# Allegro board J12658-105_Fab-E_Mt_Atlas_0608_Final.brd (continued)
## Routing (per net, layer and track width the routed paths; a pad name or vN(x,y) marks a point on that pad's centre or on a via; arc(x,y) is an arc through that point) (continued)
AP_I2C1_SCL: length 72.6
  TOP w0.127: v1(15.62,37.85) 15.62,38.1 16.04,38.52 U19.6 ; U22.D11 v1(30.98,44.37)
  L3_SIG w0.127: v1(14.59,48.38) 14.34,48.13 14.34,43.5 14.93,42.91 14.93,39.89 15.19,39.64 15.19,38.48 15.62,38.05 v1(15.62,37.85) ; v1(29.9,49.94) 29.9,47.44 30.59,46.75 30.59,44.92 30.98,44.52 v1(30.98,44.37) ; v1(14.61,12.7) 11.85,15.46 11.85,36.37 11.68,36.54 11.68,36.57 11.49,36.76 v1(11.49,38.04)
  L4_SIG w0.127: v1(15.62,37.85) 14.7,36.92 12.61,36.92 v1(11.49,38.04) ; v1(14.59,48.38) 14.79,48.38 15.02,48.61 15.2,48.61 15.95,49.36 17.84,49.36 18.03,49.18 18.16,49.05 19.25,49.05 19.89,49.05 20.28,48.66 22.25,48.66 22.74,49.15 24.79,49.15 25.16,49.52 27.82,49.52 28.22,49.12 28.77,49.12 29.59,49.94 v1(29.9,49.94)
  BOTTOM w0.127: R244.1 v1(14.61,12.7) ; R179.2 29.23,45.89 30.02,45.89 30.59,45.32 30.59,44.88 30.98,44.48 v1(30.98,44.37)
AP_I2C1_SCL_HDR: length 13.3
  BOTTOM w0.203: R244.2 12.51,12.7 10.9,11.09 9.5,11.09 8.95,10.54 8.95,9.4 8.45,8.89 3.81,8.89 J15.39
AP_I2C1_SDA: length 72.9
  TOP w0.127: U19.3 21,40.47 v1(21.59,39.88) ; U22.C11 v1(30.18,44.37)
  L3_SIG w0.127: v1(21.59,39.88) 23.79,42.08 23.79,44.83 24.31,45.34 v1(24.64,45.34) ; v1(7.9,40.79) 7.48,40.37 7.48,37.22 8.34,36.36 8.34,35.06 8.25,34.97 8.25,26.49 8.34,26.39 8.34,26 7.98,25.63 7.98,25.57 7.97,25.56 7.97,13.05 7.98,13.04 7.98,12.98 9.73,11.23 10.81,11.23 12.24,9.8 14.01,9.8 v1(14.67,9.14)
  L4_SIG w0.127: v1(7.9,40.79) 9.24,39.44 13.41,39.44 14.24,40.27 21.01,40.27 21.41,39.88 v1(21.59,39.88) ; v1(30.18,44.37) 30.1,44.37 29.7,44.77 29.23,44.77 28.99,45 28.99,45.32 28.58,45.73 25.03,45.73 v1(24.64,45.34)
  BOTTOM w0.127: R256.1 v1(14.67,9.14) ; R182.2 25.53,45.72 25.15,45.34 v1(24.64,45.34)
AP_I2C1_SDA_HDR: length 12.7
  BOTTOM w0.203: R256.2 12.51,9.14 11.3,7.94 11.3,7.11 10.7,6.51 3.97,6.51 2.54,5.08
AP_I2C1_SS_SCL: length 106
  TOP w0.127: U22.D10 v1(30.98,43.57) ; U19.5 18.36,39.17 v1(18.67,38.86) ; R116.2 54.8,11.43 v1(54.74,11.37) ; v1(22.96,48.63) 22.99,48.66 R30.1
  L3_SIG w0.127: v1(18.86,9.27) 18.86,9.33 19.11,9.58 19.11,10.86 18.85,11.13 18.85,16.81 19.04,17 19.04,27.32 17.92,28.44 17.92,31.92 18.26,32.26 18.54,32.26 18.88,32.6 18.88,32.96 18.28,33.57 18.28,34.18 18.81,34.71 18.81,35.93 18.28,36.46 18.28,36.99 18.62,37.34 18.72,37.34 19.06,37.68 19.06,38.47 v1(18.67,38.86) 17.26,40.27 v1(17.26,48.9) ; v1(30.98,43.57) 30.98,43.74 30.58,44.14 30.58,44.53 30.35,44.76 30.02,44.76 29.78,45 29.78,45.97 28.26,47.5 v1(28.26,48.26) ; v1(54.74,11.37) 54.74,12.32 54.46,12.6 53.67,12.6 52.88,11.81 52.88,10.57 53.02,10.43 v1(53.02,9.62)
  L4_SIG w0.127: v1(17.26,48.9) 17.35,48.82 18.07,48.82 19.16,48.82 19.16,48.82 19.8,48.82 20.18,48.43 20.32,48.43 22.76,48.43 v1(22.96,48.63) 24.59,48.63 25.26,49.29 26.03,49.29 26.43,48.89 27.63,48.89 v1(28.26,48.26) ; v1(53.02,9.62) 52.68,9.62 52.62,9.68 48.39,9.68 47.87,9.16 47.01,9.16 46.58,9.59 37.15,9.59 37.02,9.46 19.24,9.46 19.05,9.27 v1(18.86,9.27)
  BOTTOM w0.127: R187.2 v1(18.67,38.86)
AP_I2C1_SS_SCL_HDR: length 10.2
  TOP w0.203: J14.44 64.77,11.43 R116.1
AP_I2C1_SS_SCL_IMU: length 2.6
  TOP w0.127: R30.2 R28.2 24.33,50.8 24.58,50.55 U14.3
AP_I2C1_SS_SDA: length 111.5
  TOP w0.127: v1(24.64,51.97) 23.91,52.7 R25.1 ; U22.C10 v1(30.18,43.57) ; R112.2 v1(54.61,13.78) ; U19.2 18.44,41.12 v1(18.67,40.89)
  L3_SIG w0.127: v1(24.64,51.97) 26.61,50 26.61,47.37 28.02,45.96 28.02,45.17 28.43,44.76 28.74,44.76 28.98,44.52 28.98,44.21 29.22,43.97 29.6,43.97 30,43.57 v1(30.18,43.57) ; v1(18.41,6.47) 19.3,7.36 19.3,9.45 19.34,9.49 19.34,10.96 19.21,11.09 19.09,11.21 19.09,16.73 19.27,16.9 19.27,27.41 18.15,28.53 18.15,31.09 18.52,31.46 18.58,31.46 19.13,32.01 19.13,37.33 19.29,37.49 19.29,39.06 18.97,39.38 18.97,40.59 v1(18.67,40.89) ; v1(52.32,8.95) 52.32,9.52 52.62,9.82 52.62,11.87 53.58,12.83 54.08,12.83 54.61,13.36 v1(54.61,13.78) ; v1(24.32,40.54) 24.32,40.89 25.03,41.6 25.03,41.94 24.68,42.3 24.68,44.37 v1(24.39,44.66)
  L4_SIG w0.127: v1(52.32,8.95) 51.37,8 49.44,8 48.59,7.15 37.47,7.15 36.32,8.29 34.11,8.29 32.68,6.86 18.8,6.86 18.42,6.47 v1(18.41,6.47) ; v1(24.39,44.66) 25.13,44.66 25.41,44.95 26.53,44.95 26.71,44.76 28.75,44.76 28.98,44.53 28.98,44.22 29.22,43.97 29.78,43.97 v1(30.18,43.57) ; v1(24.32,40.54) 24.27,40.49 22.6,40.49 22.59,40.5 21.43,40.5 21.04,40.89 v1(18.67,40.89)
  BOTTOM w0.127: R191.2 v1(18.67,40.89)
AP_I2C1_SS_SDA_HDR: length 10.3
  TOP w0.203: R112.1 57.89,13.78 58.08,13.97 64.77,13.97 66.04,12.7
AP_I2C1_SS_SDA_IMU: length 3
  TOP w0.127: R24.2 R25.2 24.64,51.05 U14.2
AP_JTAG_TCK: length 25.7
  TOP w0.127: v1(31.5,56.26) 31.8,56.57 U13.15 ; U22.G2 v1(34.18,37.17)
  L3_SIG w0.127: v1(34.18,37.17) 33.27,38.08 33.27,39.06 33.44,39.22 33.44,39.93 33.35,40.01 33.35,45.9 31.69,47.56 31.69,49.78 30.76,50.71 30.76,55.83 31.19,56.26 v1(31.5,56.26)
  BOTTOM w0.127: v1(31.5,56.26) 30.99,56.77 30.99,57.91 30.86,58.04 R274.1
AP_JTAG_TDI: length 28.3
  TOP w0.127: U13.14 31.8,56.97 v1(31.5,57.28) ; U22.G4 v1(34.18,38.77)
  L3_SIG w0.127: v1(31.5,57.28) 30.96,57.28 30.53,56.84 30.53,50.61 31.43,49.71 31.43,47.43 33.12,45.75 33.12,39.92 33.21,39.83 33.21,39.31 33.02,39.12 33.02,37.86 33.69,37.19 33.69,37.05 34.08,36.66 34.33,36.66 34.58,36.91 34.58,38.37 v1(34.18,38.77)
  BOTTOM w0.127: v1(31.5,57.28) 32.26,57.28 R129.2
AP_JTAG_TDO: length 26.5
  TOP w0.127: v1(47.56,45.08) 48.49,45.08 U17.13 ; U22.H3 v1(34.98,37.17)
  L3_SIG w0.127: v1(34.87,46.69) 35.51,46.06 35.51,45.1 35.38,44.97 35.38,41.66 34.58,40.86 34.58,39.4 34.82,39.16 35.15,39.16 35.38,38.93 35.38,37.73 34.98,37.33 v1(34.98,37.17)
  L4_SIG w0.127: v1(34.87,46.69) 41.19,46.69 42.42,45.47 46.79,45.47 46.83,45.43 47.22,45.43 v1(47.56,45.08)
  BOTTOM w0.254: R277.2 v1(47.56,45.08)
AP_JTAG_TMS: length 25.6
  TOP w0.127: U22.G3 v1(34.18,37.97) ; U13.13 32.17,57.37 31.88,57.66 31.88,57.91 v1(31.5,58.29)
  L3_SIG w0.127: v1(34.18,37.97) 33.58,38.57 33.58,39.04 33.67,39.13 33.67,40.02 33.58,40.11 33.58,46.05 31.94,47.69 31.94,49.85 30.99,50.8 30.99,55.65 31.09,55.75 31.7,55.75 32.1,56.16 32.1,57.56 31.5,58.17 v1(31.5,58.29)
  BOTTOM w0.127: v1(31.5,58.29) 31.75,58.55 R275.2
AP_JTAG_TRST_N: length 28.1
  TOP w0.127: U22.G1 33.78,35.24 v1(33.85,35.18) ; U13.12 v1(32.93,58.29)
  L3_SIG w0.127: v1(32.93,58.29) 33.99,57.23 33.99,54.21 36.18,52.02 36.18,41.66 35.39,40.87 35.39,39.4 35.67,39.13 35.67,37.61 35.39,37.33 35.39,37.02 33.85,35.47 v1(33.85,35.18)
  BOTTOM w0.127: v1(32.93,58.29) 32.64,58.58 R276.1
AP_PWRGOOD: length 29.5
  TOP w0.127: v1(45.97,44.77) 45.4,44.77 45.01,45.16 U26.1 ; U22.G5 v1(34.18,39.57)
  L3_SIG w0.127: v1(45.97,44.77) 45.97,44.45 47.62,42.8 47.62,37.78 48.13,37.27 48.13,36.26 47.82,35.94 47.13,35.94 v1(47.12,35.95)
  L4_SIG w0.127: v1(34.18,39.57) 34.59,39.16 34.59,37.8 34.82,37.57 37.65,37.57 39.34,35.89 42.66,35.89 43.6,34.95 46.11,34.95 v1(47.12,35.95)
AP_PWRGOOD_SENSE: length 2.4
  TOP w0.203: U26.2 45.66,46 45.81,45.85 C101.1
  TOP w0.254: R5.2 C101.1
AP_RESET_N: length 85.2
  TOP w0.127: v1(64.64,70.87) 64.14,70.87 63.82,71.18 63.82,71.5 63.38,71.94 U36.4
  L3_SIG w0.127: v1(21.59,40.9) 22.01,40.9 23.5,42.39 23.5,46.04 22.45,47.08 22.45,48.9 22.78,49.23 22.78,53.89 22.23,54.45 22.23,62.94 21.35,63.82 21.35,64.53 21.72,64.9 v1(21.72,66.46)
  L4_SIG w0.127: v1(21.72,66.46) 22.81,66.46 23.48,67.13 24.82,67.13 25.51,66.44 34.64,66.44 34.79,66.6 50.85,66.6 52.13,67.88 52.13,68.58 52.58,69.02 56.06,69.02 56.72,69.68 59.73,69.68 60.59,68.82 62.08,68.82 62.87,69.61 62.87,69.65 64.09,70.87 v1(64.64,70.87)
  BOTTOM w0.127: U32.2 65.96,68.37 65.6,68.01 64.45,68.01 64.07,68.39 64.07,70.23 64.64,70.8 v1(64.64,70.87) 65.26,70.25 U32.5 ; v1(21.59,40.9) 21.6,40.89 R281.1
AP_RESET_N_R: length 10.4
  TOP w0.127: U22.E5 32.18,39.17 v1(31.79,38.77)
  L4_SIG w0.127: v1(25.07,40.99) 25.27,40.79 26.46,40.79 27.04,40.21 30.9,40.21 31.38,39.73 31.38,39.18 v1(31.79,38.77)
  BOTTOM w0.127: v1(25.07,40.99) 24.2,40.99 24.1,40.89 R281.2
AP_RESET_N_VSYS: length 4.3
  TOP w0.127: v1(63.44,69.66) 63.38,69.72 U36.3
  BOTTOM w0.127: v1(63.44,69.66) 63.82,70.04 63.82,70.62 64.82,71.62 U31.1
AP_SPI0_SS_CS0_N: length 42.7
  TOP w0.127: v1(26.62,53.57) 26.78,53.57 27.41,52.95 27.41,52.55 27.11,52.25 U14.12 ; v1(25.1,42.43) 25.36,42.7 28.65,42.7 U22.A9 ; R41.1 10.05,44.83 10.16,44.72 v1(10.16,42.16)
  L3_SIG w0.127: v1(23.24,53.59) 23.24,53.36 23.12,53.24 23.12,50.3 23.43,49.99 23.43,47.95 23.43,47.55 23.43,47.36 25.1,45.69 v1(25.1,42.43)
  L4_SIG w0.127: v1(26.62,53.57) 26.28,53.91 23.56,53.91 v1(23.24,53.59) ; v1(25.1,42.43) 25.1,41.68 24.77,41.35 11.29,41.35 10.48,42.16 v1(10.16,42.16)
  BOTTOM w0.127: v1(26.62,53.57) 26.68,53.57 26.7,53.59 R152.2
AP_SPI0_SS_CS0_N_HDR: length 6.6
  TOP w0.203: R41.2 6.48,44.83 6.1,44.45 3.81,44.45 J15.9
AP_SPI0_SS_CS1_N: length 27.7
  TOP w0.127: U22.D9 v1(30.98,42.77) ; v1(14.86,43.56) 14.86,42.48 13.91,41.53 R46.1
  L4_SIG w0.127: v1(14.86,43.56) 15.57,42.85 16.92,42.85 17.69,42.08 20.96,42.08 21.32,42.44 21.32,42.58 21.55,42.81 21.69,42.81 22.26,43.38 27.08,43.38 28.09,42.37 30.5,42.37 30.89,42.77 v1(30.98,42.77)
  BOTTOM w0.127: R180.2 27.93,46.17 28.55,46.17 29.16,45.56 29.55,45.56 29.79,45.32 29.79,45 30.03,44.76 30.35,44.76 30.59,44.52 30.59,43.16 v1(30.98,42.77)
AP_SPI0_SS_CS1_N_HDR: length 10.5
  TOP w0.203: J15.11 3.81,41.91 5.97,41.91 6.22,41.66 11.58,41.66 11.71,41.53 R46.2
AP_SPI0_SS_CS2_N_GPIO29: length 69.8
  TOP w0.127: v1(15.75,43.56) 15.75,42.93 14.99,42.17 14.99,40.16 14.33,39.5 R50.1 ; R86.1 v1(43.05,25.65) ; U22.B9 v1(29.38,42.77)
  L3_SIG w0.127: v1(15.75,43.56) 16.24,43.07 16.24,39.71 16.32,39.63 16.32,32.58 15.43,31.69 15.43,31.13 15.44,31.12 15.44,30.79 15.43,30.78 v1(15.43,29.46) ; v1(41.66,28.96) 41.66,27.05 v1(43.05,25.65)
  L4_SIG w0.127: v1(41.66,28.96) 40.4,28.96 39.97,29.39 34.7,29.39 34.46,29.15 25.89,29.15 25.45,28.7 21.44,28.7 21.09,29.04 21.09,29.05 20.69,29.46 v1(15.43,29.46) ; v1(29.38,42.77) 28.02,42.77 27.53,43.26 27.18,43.61 22.36,43.61 22.35,43.62 22.16,43.62 21.59,43.05 21.46,43.05 21.08,42.67 21.08,42.54 20.84,42.3 17.79,42.3 16.53,43.56 v1(15.75,43.56)
  BOTTOM w0.127: R193.2 28.16,42.77 v1(29.38,42.77)
AP_SPI0_SS_CS2_N_GPIO29_HDR: length 10.3
  TOP w0.203: J15.13 3.8,39.38 11.63,39.38 11.75,39.5 12.32,39.5
AP_SPI0_SS_CS3_N_GPIO30: length 60.7
  TOP w0.127: v1(31.43,21.46) 31.88,21.46 32.2,21.79 U25.13 ; R56.1 v1(13.84,36.45) ; U22.C8 v1(30.18,41.97)
  L3_SIG w0.127: v1(13.84,36.45) 13.56,36.73 13.56,36.92 13.28,37.2 13.28,37.23 13.28,37.23 13.28,38.93 13.27,38.94 13.27,39.19 13.22,39.24 13.12,39.34 13.12,40.82 13.22,40.92 13.22,40.93 13.97,41.68 v1(13.97,42.54) ; v1(30.18,41.97) 30.18,41.78 30.58,41.39 30.58,41 29.71,40.13 28.59,40.13 27.5,39.05 27.5,37.99 26.67,37.15 26.67,36.71 26.35,36.4 26.35,35.49 26.36,35.49 26.36,32.84 24.54,31.02 24.54,29.53 22.75,27.74 22.75,27.47 22.72,27.44 22.72,23 v1(24.13,21.59)
  L4_SIG w0.127: v1(31.43,21.46) 30.68,22.21 30.6,22.29 24.83,22.29 v1(24.13,21.59) ; v1(13.97,42.54) 14.3,42.21 16.58,42.21 16.81,41.98 17.17,41.62 23.56,41.62 v1(24.25,42.32)
  BOTTOM w0.127: v1(30.18,41.97) 30.07,41.97 29.67,42.36 28.42,42.36 28.35,42.29 R194.2 27.54,42.29 27.1,42.74 26.02,42.74 25.78,42.98 24.91,42.98 v1(24.25,42.32)
AP_SPI0_SS_CS3_N_GPIO30_HDR: length 10.5
  TOP w0.203: 12.32,36.45 11.68,36.45 11.46,36.66 3.98,36.66 J15.15
AP_SPI0_SS_MISO: length 32.9
  TOP w0.127: U22.A10 v1(28.58,43.57) ; U14.1 25.34,52.06 v1(24.57,52.83) ; R32.1 9.91,49.66 10.16,49.4 v1(10.16,49.09)
  L3_SIG w0.127: v1(24.57,52.83) 24.38,52.64 24.37,52.64 23.96,52.23 23.96,51.44 25.1,50.3 25.1,49.49 24.74,49.13 24.74,48.31 26.89,46.16 26.89,44.89 28.21,43.57 v1(28.58,43.57)
  L4_SIG w0.127: v1(10.16,49.09) 14.95,49.09 16.36,50.5 17.36,50.5 18.27,49.58 19.52,49.58 19.83,49.9 21.66,49.9 21.95,49.61 22.37,49.61 22.95,50.18 22.95,51.21 v1(24.57,52.83)
AP_SPI0_SS_MISO_HDR: length 6.4
  TOP w0.203: J15.5 3.68,49.66 R32.2
AP_SPI0_SS_MOSI: length 36.1
  TOP w0.127: R37.1 9.91,47.12 v1(10.16,47.37) ; U22.B10 v1(29.38,43.57) ; U14.14 26.11,52.32 v1(25.59,52.83)
  L3_SIG w0.127: v1(25.59,52.83) 25.17,52.41 24.46,52.41 24.19,52.14 24.19,51.76 25.33,50.62 25.33,49.34 24.97,48.98 24.97,48.55 27.34,46.18 27.34,45.42 27.93,44.83 27.93,44.25 28.23,43.96 28.86,43.96 29.25,43.57 v1(29.38,43.57)
  L4_SIG w0.127: v1(10.16,47.37) 9.59,47.94 9.59,48.45 9.78,48.64 10.48,48.64 10.99,48.13 13.53,48.13 14.23,48.84 15.02,48.84 15.78,49.59 17.94,49.59 18.17,49.36 19.62,49.36 19.93,49.67 21.57,49.67 21.85,49.38 22.6,49.38 25.59,52.37 v1(25.59,52.83)
AP_SPI0_SS_MOSI_HDR: length 6.5
  TOP w0.203: J15.7 3.78,47.02 5.89,47.02 5.99,47.12 R37.2
AP_SPI0_SS_SCK: length 33.9
  TOP w0.127: U22.C9 v1(30.18,42.77) ; v1(10.16,51.5) 9.78,51.88 9.52,51.88 R23.1 ; U14.13 26.61,52.38 v1(27,52.78)
  L3_SIG w0.127: v1(27,52.78) 27.53,52.25 27.53,47.27 28.99,45.81 28.99,45 29.23,44.77 29.54,44.77 29.78,44.52 29.78,44.21 30.03,43.96 30.34,43.96 30.58,43.72 30.58,43.17 v1(30.18,42.77)
  L4_SIG w0.127: v1(27,52.78) 26.58,52.78 26.44,52.92 26.44,53.18 25.94,53.68 24.22,53.68 22.98,52.44 21.49,52.44 20.97,52.95 16.88,52.95 15.98,52.06 15.32,52.06 14.79,52.58 11.24,52.58 v1(10.16,51.5)
AP_SPI0_SS_SCK_HDR: length 6.4
  TOP w0.203: J15.3 3.8,52.08 7.43,52.08 R23.2
AP_SPI1_SS_CS0_N: length 38
  TOP w0.127: R93.1 v1(13.84,24.13) ; U23.2 v1(18.41,35.03) ; U22.C7 v1(30.18,41.17)
  L3_SIG w0.127: v1(18.41,35.03) 17.26,33.87 17.26,30.59 16.8,30.14 16.8,26.76 17.97,25.59 v1(17.97,25.08) ; v1(25.97,34.75) 25.97,36.41 26.44,36.88 26.44,37.25 26.44,37.25 27.22,38.03 27.22,39.09 27.28,39.14 27.28,39.23 28.4,40.36 28.5,40.36 28.52,40.39 29.4,40.39 v1(30.18,41.17)
  L4_SIG w0.127: v1(13.84,24.13) 17.46,24.13 17.97,24.64 v1(17.97,25.08) ; v1(25.97,34.75) 22.66,34.75 21.99,35.42 21.06,35.42 20.86,35.22 19.17,35.22 18.97,35.03 v1(18.41,35.03)
  BOTTOM w0.127: v1(30.18,41.17) 29.53,40.51 27.87,40.51 R201.2
AP_SPI1_SS_CS0_N_HDR: length 10.5
  TOP w0.203: J15.25 3.81,24.13 7.49,24.13 7.75,23.88 11.18,23.88 11.43,24.13 12.32,24.13
AP_SPI1_SS_CS1_N: length 33.1
  TOP w0.127: U22.A7 v1(28.58,41.17)
  L3_SIG w0.127: v1(22.03,23.62) 22.33,23.92 22.33,26.21 21.83,26.71 21.83,27.21 22.29,27.67 22.29,27.93 24.04,29.68 24.04,31.76 24.26,31.98 24.26,32.21 25.58,33.53 25.58,33.92 25.11,34.38 25.11,37.12 24.88,37.35 24.88,38.41 25.29,38.82 26.22,38.82 28.56,41.17 v1(28.58,41.17)
  L4_SIG w0.127: v1(22.03,23.62) 21.65,23.24 v1(13.84,23.24)
  BOTTOM w0.127: v1(28.58,41.17) 28.24,41.17 28.13,41.27 R200.2 ; v1(13.84,23.24) 13.97,23.11 R217.1
AP_SPI1_SS_CS1_N_HDR: length 15.2
  BOTTOM w0.203: J15.27 3.68,21.72 10.54,21.72 12.51,23.69 15.81,23.69 16,23.5 R217.2
AP_SPI1_SS_CS2_N_UART0_CTS_N: length 95.8
  TOP w0.127: U22.D8 v1(30.98,41.97) ; v1(21.81,21.15) 22.23,20.73 R266.1 ; v1(58.93,55.88) R19.1
  L3_SIG w0.127: v1(29.46,61.21) 30,60.68 30,54.58 30.07,54.51 30.07,53.75 30.07,50.42 30.92,49.57 30.92,46.8 31.36,46.36 31.36,45.48 31.38,45.47 31.38,45.14 31.38,45.14 31.38,42.6 31.36,42.59 31.36,42.35 v1(30.98,41.97) ; v1(21.72,42.42) 21.2,41.9 21.2,38.77 22.09,37.88 22.09,34.86 20.85,33.63 20.85,32.08 21.08,31.85 21.08,31.06 22,30.15 22,28.93 21.37,28.31 21.37,28.05 20.92,27.59 20.92,22.81 21.81,21.92 v1(21.81,21.15)
  L4_SIG w0.127: v1(58.93,55.88) 58.93,55.94 58.36,56.52 58.36,59.75 53.38,64.73 48.52,64.73 45.55,61.76 39.46,61.76 39.27,61.76 38.46,60.94 29.73,60.94 v1(29.46,61.21)
  BOTTOM w0.127: v1(30.98,41.97) 30.58,42.37 30.02,42.37 29.79,42.6 29.79,42.93 29.79,43.4 29.79,43.4 29.79,43.72 29.55,43.96 27.98,43.96 R190.2 27.18,44.77 25.34,44.77 24.7,44.13 22.61,44.13 21.72,43.24 v1(21.72,42.42)
AP_SPI1_SS_CS2_N_UART0_CTS_N_BLE: length 5.5
  TOP w0.127: R266.2 20.64,20 20.19,19.56 20.19,16.51 20.49,16.22 U30.26
AP_SPI1_SS_CS2_N_UART0_CTS_N_HDR: length 2.9
  TOP w0.203: R19.2 63.5,55.88
AP_SPI1_SS_CS3_N_UART0_RTS_N: length 80.8
  TOP w0.127: U22.D7 v1(30.98,41.17) ; R22.1 59.18,53.34 58.99,53.15 v1(58.99,52.9) ; R267.1 20.51,20.57 v1(21.08,21.15)
  L3_SIG w0.127: v1(58.99,52.9) 60.13,51.76 60.13,43.76 60.01,43.64 60.01,42.84 60.48,42.37 60.48,40.03 v1(60.2,39.75) ; v1(21.61,39.16) 22.31,38.46 22.31,33.98 21.08,32.74 21.08,32.19 21.69,31.57 21.75,31.57 22.22,31.1 22.22,28.84 21.6,28.22 21.6,27.96 21.15,27.5 21.15,22.9 22.2,21.85 22.2,20.99 21.97,20.76 21.47,20.76 v1(21.08,21.15)
  L4_SIG w0.127: v1(30.98,41.17) 31.39,40.76 36.75,40.76 37.31,40.2 38.63,40.2 41.08,37.76 49.92,37.76 50.73,38.56 59.18,38.56 59.89,39.28 59.89,39.45 v1(60.2,39.75)
  BOTTOM w0.127: v1(21.61,39.16) 22.1,38.67 27.62,38.67 R202.2 28.64,40.26 30.07,40.26 v1(30.98,41.17)
AP_SPI1_SS_CS3_N_UART0_RTS_N_BLE: length 7.1
  TOP w0.127: R267.2 19.49,16.13 19.43,16.07 19.43,15.49 20.11,14.82 U30.28
AP_SPI1_SS_CS3_N_UART0_RTS_N_HDR: length 2.9
  TOP w0.203: R22.2 63.5,53.34
AP_SPI1_SS_MISO: length 27.5
  TOP w0.127: U23.11 21.8,32.43 21.78,32.44 v1(21.7,32.44) ; R75.1 v1(13.84,28.19) ; U22.A8 v1(28.58,41.97)
  L3_SIG w0.127: v1(28.58,41.97) 27.67,41.97 26.47,40.77 25.99,40.77 23.51,38.29 23.51,34.25 v1(21.7,32.44)
  L4_SIG w0.127: v1(13.84,28.19) 13.45,28.59 13.45,30.02 15.04,31.61 16.78,31.61 18.33,33.16 20.99,33.16 v1(21.7,32.44)
AP_SPI1_SS_MISO_HDR: length 10.7
  TOP w0.203: 12.32,28.19 11.87,28.19 11.05,29.02 4,29.02 J15.21
AP_SPI1_SS_MOSI: length 30.6
  TOP w0.127: U23.5 18.36,33.08 18.49,32.94 v1(18.49,32.77) ; R79.1 v1(13.84,26.16) ; U22.B7 v1(29.38,41.17)
  L3_SIG w0.127: v1(17.2,29.02) 17.2,29.83 17.49,30.12 17.49,31.8 18.45,32.77 v1(18.49,32.77) ; v1(29.38,41.17) 28.88,40.67 28.39,40.67 27.05,39.33 27.05,39.3 26.24,38.49 25.28,38.49 25.11,38.32 25.11,37.52 25.34,37.28 25.34,34.48 25.81,34.02 25.81,33.2 v1(24.65,32.05)
  L4_SIG w0.127: v1(18.49,32.77) 20.49,32.77 20.59,32.67 20.91,32.67 21.53,32.05 v1(24.65,32.05) ; v1(17.2,29.02) 17.2,28.96 14.4,26.16 v1(13.84,26.16)
AP_SPI1_SS_MOSI_HDR: length 10.5
  TOP w0.203: J15.23 3.94,26.54 10.92,26.54 11.3,26.16 12.32,26.16
AP_SPI1_SS_SCK: length 24.8
  TOP w0.127: v1(25.19,33.75) 24.56,34.38 U23.14 21.9,34.38 21.5,33.98 v1(21.5,33.72) ; U22.B8 v1(29.38,41.97) ; R69.1 v1(14.73,31.88)
  L3_SIG w0.127: v1(29.38,41.97) 28.98,41.57 28.13,41.57 26.3,39.74 25.76,39.74 24.53,38.51 24.53,37.19 24.82,36.91 24.82,34.36 24.83,34.34 24.83,34.34 24.89,34.29 24.89,34.05 v1(25.19,33.75)
  L4_SIG w0.127: v1(14.73,31.88) 15.97,31.88 17.48,33.39 21.17,33.39 v1(21.5,33.72)
AP_SPI1_SS_SCK_HDR: length 10.9
  TOP w0.203: R69.2 11.56,31.88 11.34,32.09 6.31,32.09 6.1,31.88 3.68,31.88 J15.19
AP_UART0_RXD_ADC18: length 93.1
  TOP w0.127: U22.E8 v1(31.78,41.97) ; R16.1 v1(59.12,58.42)
  L3_SIG w0.127: v1(59.77,41.66) 59.77,42.44 59.55,42.65 59.55,43.83 59.66,43.95 59.66,50.57 58.6,51.64 58.6,53.06 58.88,53.34 59.17,53.34 59.61,53.79 59.61,57.92 v1(59.12,58.42) ; v1(24.32,39.88) 22.86,38.42 22.86,34.2 21.31,32.65 21.31,32.28 21.79,31.8 21.85,31.8 22.45,31.2 22.45,28.74 21.83,28.12 21.83,27.86 21.37,27.4 21.37,23 22.43,21.94 22.43,19.9 22.02,19.49 22.02,15.64 v1(22.55,15.11)
  L4_SIG w0.127: v1(59.77,41.66) 59.59,41.66 58.82,40.89 56.63,40.89 54.54,38.8 47.93,38.8 47.12,37.99 41.17,37.99 38.73,40.43 37.5,40.43 36.64,41.29 34.68,41.29 34.41,41.56 32.19,41.56 v1(31.78,41.97)
  BOTTOM w0.127: v1(22.55,15.11) R239.2 ; v1(24.32,39.88) 24.71,39.88 25.6,40.76 25.6,41.42 25.9,41.72 28.08,41.72 28.23,41.57 31.39,41.57 v1(31.78,41.97) 31.39,42.36 31.39,45.76 R177.2
AP_UART0_RXD_ADC18_BLE: length 3
  TOP w0.127: U30.27 20.3,15.52 19.94,15.88 v1(19.89,15.88)
  BOTTOM w0.127: R239.1 20.32,15.11 19.89,15.55 v1(19.89,15.88)
AP_UART0_RXD_ADC18_HDR: length 2.9
  TOP w0.203: R16.2 63.5,58.42
AP_UART0_TXD_GPIO31: length 120.9
  TOP w0.127: R12.1 v1(59.12,60.96) ; U22.E9 v1(31.78,42.77)
  L3_SIG w0.127: v1(11.86,13.53) 11.39,14 11.39,35.91 11.38,35.92 11.38,36.16 10.52,37.02 10.28,37.02 9.77,37.02 9.27,37.52 9.27,38.98 9.62,39.33 10.71,39.33 11.21,39.83 11.21,41.31 10.65,41.87 10.65,44.72 12.18,46.25 12.18,49.91 v1(13.34,51.07)
  L4_SIG w0.127: v1(19.81,13.34) 19.11,14.04 15.75,14.04 14.86,13.14 12.24,13.14 v1(11.86,13.53) ; v1(13.34,51.07) 13.63,51.36 14.44,51.36 14.44,51.36 22.54,51.36 24.41,53.23 25.75,53.23 25.98,53 25.98,52.38 26.88,51.49 29.86,51.49 30.54,50.8 v1(31.56,50.8) 32.85,49.5 42.99,49.5 44.27,48.22 44.86,48.22 46.11,49.48 46.72,49.48 47.26,48.95 51.98,48.95 52.18,49.15 53.85,49.15 54.36,49.66 54.41,49.66 57.41,52.66 57.41,52.96 59.51,55.07 59.51,60.57 v1(59.12,60.96)
  BOTTOM w0.127: v1(31.78,42.77) 32.18,43.16 32.18,45.99 R176.2 31.5,46.74 32,47.24 32,50.36 v1(31.56,50.8) ; v1(19.81,13.34) 19.94,13.21 R243.2
AP_UART0_TXD_GPIO31_BLE: length 4.1
  TOP w0.127: v1(19.81,14) 19.84,14 19.96,14.12 U30.29
  BOTTOM w0.127: v1(19.81,14) 21.63,14 21.84,13.78 R243.1
AP_UART0_TXD_GPIO31_HDR: length 2.9
  TOP w0.203: R12.2 63.5,60.96
AP_USB_5V: length 28.9
  TOP w0.508: D7.2 19.49,67.12 19.24,66.87 17.21,66.87 16.32,65.98 v1(16.32,65.34) R9.1
  L4_SIG w0.508: v1(36.83,65.72) v1(35.81,65.72) 29.35,65.72 28.15,64.52 22.6,64.52 22.23,64.9 21.29,64.9 20.74,65.44 19.37,65.44 18.63,66.18 16.81,66.18 16.32,65.69 v1(16.32,65.34)
  BOTTOM w0.381: C52.1 v1(36.83,65.72) ; C53.1 v1(35.81,65.72)
AP_USB_5V_R: length 2.5
  TOP w0.254: 16.32,62.93 U7.A2
  TOP w0.508: 16.32,62.93 R9.2 C4.1
AP_USB_DN: length 20.6
  TOP w0.21: U22.M11 v1(38.18,44.37) ; L1.2 34.49,62.21 34.39,62.11 34.39,61.75 v1(34.62,61.52)
  L3_SIG w0.152: v1(38.18,44.37) 38.18,44.74 37.94,44.99 37.94,46.46 36.88,47.51 36.88,52.96 36.55,53.29 36.55,55.54 35.27,56.82 35.27,59.55 34.38,60.44 34.38,61.28 v1(34.62,61.52)
AP_USB_DP: length 22.4
  TOP w0.21: v1(33.88,61.52) 34.04,61.68 34.04,62.11 33.94,62.21 L1.3 ; U22.L11 v1(37.38,44.37)
  L3_SIG w0.152: v1(37.38,44.37) 37.38,44.74 37.63,44.99 37.63,46.33 36.58,47.39 36.58,52.83 36.25,53.16 36.25,55.41 34.97,56.69 34.97,59.42 34.08,60.31 34.08,61.32 v1(33.88,61.52)
  BOTTOM w0.203: R278.2 37.72,45.21
  BOTTOM w0.21: v1(37.38,44.37) 37.4,44.39 37.4,44.89 37.72,45.21
AP_USB_ID: length 2.6
  TOP w0.127: U34.1 33.23,70.25 J1.4
AP_VBUS: length 15.5
  TOP w0.127: v1(28.58,69.22) 28.58,74.42 D2.1
  TOP w0.254: U3.5 v1(34.2,68.83)
  L4_SIG w0.508: v1(35.75,69.66) 35.31,69.22 34.58,69.22 v1(34.2,68.83)
  BOTTOM w0.127: v1(34.2,68.83) 28.96,68.83 v1(28.58,69.22)
  BOTTOM w0.508: R11.1 v1(35.75,69.66)
ARD_A0: length 3.4
  BOTTOM w0.203: J12.1 11.11,17.78 12.26,18.92 R225.2
ARD_A1: length 3.7
  BOTTOM w0.203: R234.2 12.32,17.14 10.41,15.24 10.16,15.24
ARD_A2: length 4.2
  BOTTOM w0.203: J12.3 11.08,13.62 11.08,14 12.45,15.37 R238.2
ARD_A3: length 3.6
  BOTTOM w0.203: R248.2 12.26,10.99 11.94,10.99 11.11,10.16 J12.4
ARD_A4: length 3.9
  BOTTOM w0.203: J12.5 12.57,10.03 R254.2
ARD_A4_SPARE: length 2
  TOP w0.203: R36.1 J8.2
ARD_A5: length 4.4
  BOTTOM w0.203: R260.2 12.51,7.37 12.26,7.11 12.26,6.16 11.18,5.08 10.16,5.08
ARD_A5_SPARE: length 2.3
  TOP w0.203: J8.1 56.71,49.78 R29.1
ARD_AREF: length 2.2
  TOP w0.203: R42.1 57.91,44.2 J8.3
ARD_D0: length 3.3
  TOP w0.203: J11.1 57.4,5.08 56.39,6.1 R121.1
ARD_D1: length 2.2
  TOP w0.203: R119.1 56.9,8 57.28,7.62 J11.2
ARD_D2: length 2.1
  TOP w0.127: R111.1 58.29,10.29 J11.3
ARD_D3: length 2.1
  TOP w0.203: R115.1 57.21,12.76 57.28,12.7 J11.4
ARD_D4: length 2
  TOP w0.127: R117.1 J11.5
ARD_D5: length 2
  TOP w0.203: R109.1 J11.6
ARD_D6: length 2
  TOP w0.203: R103.1 J11.7
ARD_D7: length 2
  TOP w0.203: R95.1 58.42,22.86
ARD_D8: length 2
  TOP w0.203: R78.1 58.42,26.92
ARD_D9: length 2.2
  TOP w0.203: R72.1 57.91,29.97 J8.9
ARD_D10: length 2
  TOP w0.203: R68.1 J8.8
ARD_D11: length 2.2
  TOP w0.203: R62.1 57.91,35.05 J8.7
ARD_D12: length 4.9
  TOP w0.203: 58.42,37.08 57.91,36.58 54.48,36.58 R58.1
ARD_D13: length 2.2
  TOP w0.203: J8.5 57.4,39.62 56.9,39.12 R51.1
ARD_IOREF: length 2.4
  TOP w0.203: R52.2 10.54,38.48 10.16,38.1
ARD_RESET_N: length 87.9
  TOP w0.127: v1(13.87,35.44) 13.86,35.43 R60.1
  L3_SIG w0.127: v1(13.87,35.44) 14.19,35.76 14.19,35.98 14.24,36.03 14.24,36.61 13.76,37.09 13.75,37.09 13.51,37.33 13.51,39.37 13.45,39.43 13.45,40.74 14.36,41.66 14.36,42.76 13.88,43.24 13.88,54.7 14.99,55.81 14.99,65.52 16.52,67.06 18.15,67.06 v1(18.61,67.51)
  L4_SIG w0.127: v1(18.61,67.51) 19.13,66.98 22.95,66.98 23.33,67.36 25.02,67.36 25.71,66.67 33.5,66.67 33.78,66.96 43.09,66.96 44.03,67.91 50.36,67.91 51.22,68.77 51.94,68.77 52.51,69.34 55.82,69.34 56.39,69.91 60.14,69.91 60.34,69.71 61.73,69.71 63.35,71.33 65.5,71.33 v1(65.96,70.87)
  BOTTOM w0.127: U32.7 v1(65.96,70.87)
ARD_RESET_N_R: length 80
  TOP w0.127: 10.16,35.56 v1(7.49,35.56)
  TOP w0.203: 10.16,35.56 10.29,35.43 12.32,35.43
  L3_SIG w0.127: v1(8.45,9.91) 7.29,11.06 7.29,12.76 7.28,12.76 7.28,25.85 7.29,25.86 7.29,26.09 7.49,26.29 v1(7.49,35.56)
  L4_SIG w0.127: v1(53.85,8.13) 52.53,9.45 48.56,9.45 48.05,8.93 47.11,8.93 46.57,8.93 46.16,9.33 37.27,9.33 37.17,9.23 33.8,9.23 32.63,8.06 19.77,8.06 18.97,8.87 15.58,8.87 14.85,9.6 13.56,9.6 12.89,8.93 9.42,8.93 v1(8.45,9.91)
  BOTTOM w0.127: R259.2 v1(53.85,8.13)
ARD_RESET_N_R_HDR: length 11.8
  BOTTOM w0.203: R259.1 57.28,6.35 64.77,6.35 66.04,5.08
ARDUINO_A4: length 106.4
  TOP w0.127: U19.4 18.41,39.82 18.46,39.88 v1(18.47,39.88) ; R36.2 v1(54.74,47.24)
  L3_SIG w0.127: v1(7.94,38.48) 7.94,37.15 8.57,36.51 8.57,34.97 8.47,34.87 8.47,26.59 8.57,26.49 8.57,25.84 8.2,25.47 8.2,13.14 9.76,11.58 11.07,11.58 12.62,10.03 v1(14.67,10.03) ; v1(18.47,39.88) 17.82,40.53 17.82,51.36 17.82,52.05 v1(18.26,52.49) ; v1(55.5,51.31) 55.44,51.25 55.44,47.94 v1(54.74,47.24)
  L4_SIG w0.127: v1(18.47,39.88) 14.86,39.88 14.18,39.2 8.66,39.2 v1(7.94,38.48) ; v1(18.26,52.49) 18.71,52.49 18.95,52.73 20.88,52.73 21.39,52.21 23.07,52.21 24.32,53.45 25.85,53.45 26.21,53.09 26.21,52.83 26.65,52.38 27.71,52.38 29.06,53.73 33.75,53.73 34.2,53.29 37.77,53.29 40.72,50.34 49.74,50.34 51.01,51.61 53.76,51.61 53.93,51.78 55.02,51.78 v1(55.5,51.31)
  BOTTOM w0.127: R254.1 v1(14.67,10.03)
ARDUINO_A5: length 117.9
  TOP w0.127: U19.7 18.64,37.87 v1(18.67,37.85) ; R29.2 55.37,50.1 v1(53.09,50.1)
  L3_SIG w0.127: v1(53.09,50.1) 53.28,50.29 53.28,51.5 51.83,52.95 v1(51.83,60.12) ; v1(18.09,53.39) 16.76,52.06 16.76,51.56 17.28,51.04 17.28,49.81 16.73,49.26 16.73,45.01 16.93,44.81 16.93,40 17.16,39.77 17.51,39.42 17.51,39.01 v1(18.67,37.85) ; v1(7.49,36.22) 7.89,35.83 7.89,35.25 7.79,35.16 7.79,26.2 7.52,25.94 7.52,25.76 7.51,25.75 7.51,12.86 7.52,12.85 7.52,12.14 7.65,12.01 8.91,10.76 8.91,9.49 9.57,8.83 13.21,8.83 v1(14.67,7.37)
  L4_SIG w0.127: v1(18.67,37.85) 17.91,37.08 15.96,37.08 14.77,35.9 13.07,35.9 12.13,36.84 8.12,36.84 v1(7.49,36.22) ; v1(51.83,60.12) 51.83,58.52 48.02,54.7 45,54.7 44.99,54.71 41.8,54.71 41.18,54.09 38.91,54.09 38.56,53.75 37.13,53.75 36.06,54.81 34.94,54.81 34.51,54.38 20.85,54.38 19.86,53.39 v1(18.09,53.39)
  BOTTOM w0.127: R260.1 v1(14.67,7.37)
ARDUINO_CTS: length 86.1
  TOP w0.127: v1(21.46,43.94) 21.46,44.32 21.76,44.62 U20.11 ; v1(34.29,30.16) 33.78,30.16 33.6,29.98 33.6,29.95 33.5,29.85 U25.2 ; v1(59.05,53.78) 59.75,54.48 R21.2
  L3_SIG w0.127: v1(21.46,43.94) 21.46,43.22 20.97,42.72 20.97,38.67 21.86,37.79 21.86,35.65 21.4,35.19 21.3,35.19 20.94,34.83 20.94,34.39 20.62,34.07 20.62,31.99 20.86,31.75 20.86,30.91 21.66,30.11 21.66,29.15 v1(21.6,29.09) ; v1(59.31,30.61) 59.44,30.73 59.44,35.2 59,35.64 59,36.25 59.49,36.73 59.49,40.28 59.31,40.46 59.31,41.81 59.49,41.99 59.49,42.39 59.31,42.57 59.31,43.99 59.44,44.12 59.44,50.48 58.32,51.59 58.32,53.49 58.62,53.78 v1(59.05,53.78)
  L4_SIG w0.127: v1(59.31,30.61) 56.9,30.61 55.91,29.62 52.58,29.62 52.16,29.2 51.17,29.2 50.98,29.39 45.85,29.39 45.25,29.98 44.92,29.98 44.69,29.75 44.69,29.72 44.42,29.45 40.25,29.45 40.01,29.69 34.89,29.69 34.42,30.16 v1(34.29,30.16) 33.63,29.5 24.23,29.5 23.79,29.06 21.64,29.06 v1(21.6,29.09)
ARDUINO_IO_0_UART_RXD: length 136.1
  TOP w0.127: U20.5 18.22,45.27 18.41,45.47 19.43,45.47 19.8,45.09 v1(19.8,43.95) ; v1(53.91,7.18) 54.1,6.98 R121.2 ; R18.2 v1(58.93,57.15)
  L3_SIG w0.127: v1(53.91,7.18) 53.91,7.37 56.03,9.48 56.03,44.54 54.91,45.66 54.78,45.66 54.47,45.97 54.47,46.3 55.94,47.77 55.94,52.2 57.21,53.47 57.53,53.47 58.51,54.45 58.51,56.73 v1(58.93,57.15) ; v1(19.8,43.95) 19.45,43.61 19.45,39.82 19.75,39.53 19.75,37.3 19.59,37.14 19.59,31.58 20.3,30.87 20.3,30.54 20.23,30.46 20.23,19.38 20.51,19.09 20.51,7.73 v1(19.21,6.43)
  L4_SIG w0.127: v1(19.21,6.43) 32.72,6.43 34.35,8.06 35.95,8.06 37.37,6.64 43.32,6.64 44.14,5.82 46.49,5.82 46.73,6.05 48.34,6.05 49.8,7.51 53.57,7.51 v1(53.91,7.18)
ARDUINO_IO_1_UART_TXD: length 163.4
  TOP w0.127: R119.2 54.94,7.44 v1(54.61,7.44) ; R14.2 v1(58.93,59.69) ; v1(20.07,45.97) 19.3,46.74 19.3,47.24 19.05,47.5 18.41,47.5 18.13,47.22 U20.2
  L3_SIG w0.127: v1(8.56,44.04) 8.56,37.29 8.59,37.26 8.59,37.24 9.04,36.78 9.04,34.94 9.03,34.92 9.03,34.78 8.93,34.68 8.93,26.78 9.11,26.6 9.11,24.89 8.97,24.75 8.97,14.2 9.29,13.87 10.52,13.87 11.41,12.99 11.41,12.74 13.67,10.47 15.12,10.47 v1(15.56,10.03) ; v1(59.77,8.03) 59.44,8.36 59.44,15.19 59.42,15.2 59.42,15.53 59.44,15.54 59.44,18.47 59.49,18.52 59.49,24.05 57.4,26.14 57.4,37.46 57.96,38.02 57.96,38.63 57.2,39.4 57.2,40.74 57.45,41 57.45,48.21 57.68,48.44 57.68,49.15 56.36,50.47 56.36,52.3 57.15,53.09 57.59,53.09 59.39,54.88 59.39,57.38 58.47,58.29 58.47,58.7 58.93,59.16 v1(58.93,59.69)
  L4_SIG w0.127: v1(15.56,10.03) 16.07,10.54 16.51,10.54 17.4,11.43 26.57,11.43 27.57,10.43 33.17,10.43 33.29,10.55 34.53,10.55 34.94,10.15 46.22,10.15 47.45,11.38 53.63,11.38 54.61,10.4 v1(54.61,7.44) 55.8,7.44 56.87,8.51 59.28,8.51 v1(59.77,8.03) ; v1(8.56,44.04) 9.41,44.89 18.03,44.89 18.36,44.56 18.98,44.56 19.44,45.02 19.53,45.02 20.07,45.55 v1(20.07,45.97)
ARDUINO_IO_2: length 48.9
  TOP w0.127: U25.7 30.25,27.33 v1(30.23,27.3) ; R111.2 54.67,10.29 v1(53.91,9.52)
  L3_SIG w0.127: v1(30.23,27.3) 30.23,26.63 29.72,26.13 29.72,23.75 28.33,22.36 28.33,21.43 v1(28.05,21.14) ; v1(53.91,9.52) 52.64,8.25 51.75,8.25 50.83,9.18 v1(50.83,19.67)
  L4_SIG w0.127: v1(50.83,19.67) 40.1,19.67 39.82,19.4 33.98,19.4 33.62,19.04 30.16,19.04 v1(28.05,21.14)
ARDUINO_IO_3: length 45
  TOP w0.127: R115.2 54.04,12.76 53.85,12.95 v1(53.85,13.27) ; v1(26.16,27.3) 26.11,27.36 U28.4
  L3_SIG w0.127: v1(26.16,27.3) 25.62,26.77 25.62,25.68 24.75,24.81 24.75,23.42 25.95,22.22 25.95,20.88 26.29,20.55 v1(27.31,20.55) ; v1(51.27,18.14) 51.27,14.45 52.45,13.27 v1(53.85,13.27)
  L4_SIG w0.127: v1(51.27,18.14) 50.34,19.06 47.88,19.06 47.35,18.53 40.54,18.53 39.91,19.17 34.07,19.17 33.71,18.81 29.91,18.81 28.17,20.55 v1(27.31,20.55)
ARDUINO_IO_4: length 36.1
  TOP w0.127: v1(34.54,25.96) 34.18,26.31 33.25,26.31 32.2,27.36 U25.4 ; R117.2 v1(54.8,15.24)
  L3_SIG w0.127: v1(34.54,25.96) 35.17,25.33 35.17,17.14 v1(34.54,16.52)
  L4_SIG w0.127: v1(54.8,15.24) 53.95,15.24 53.64,14.93 48.87,14.93 48.74,15.06 38.98,15.06 38.12,15.92 35.15,15.92 v1(34.54,16.52)
ARDUINO_IO_5: length 42
  TOP w0.127: U28.7 24.16,27.33 v1(24.13,27.3) ; R109.2 v1(53.85,17.78)
  L3_SIG w0.127: v1(24.13,27.3) 23.69,26.86 23.69,25.78 24.51,24.96 24.51,23.34 25.72,22.13 25.72,19.46 v1(25.98,19.2)
  L4_SIG w0.127: v1(53.85,17.78) 53.15,17.78 53.14,17.79 51.77,17.79 51.72,17.74 50.93,17.74 50.5,18.17 48.08,18.17 47.29,17.39 40.74,17.39 39.35,18.77 34,18.77 33.81,18.58 29.62,18.58 28.63,19.57 26.35,19.57 v1(25.98,19.2)
ARDUINO_IO_6: length 36.7
  TOP w0.127: v1(53.85,20.26) 53.91,20.32 R103.2 ; v1(23.11,24.51) 23.51,24.12 U28.9
  L4_SIG w0.127: v1(23.11,24.51) 24.65,22.98 33.65,22.98 34.47,22.16 38.73,22.16 39.22,21.68 44.85,21.68 45.52,22.35 50.34,22.35 50.39,22.3 50.39,22.3 50.62,22.07 50.62,22.07 50.65,22.04 50.65,21.58 51.05,21.17 52.93,21.17 v1(53.85,20.26)
ARDUINO_IO_7: length 29.1
  TOP w0.127: U25.9 29.6,24.12 v1(29.21,24.51) ; R95.2 v1(54.74,22.86)
  L4_SIG w0.127: v1(29.21,24.51) 29.73,23.99 33.93,23.99 34.03,23.89 40.52,23.89 40.56,23.93 41.63,23.93 41.74,23.81 50.15,23.81 50.62,23.35 50.62,23.18 51.34,22.47 54.34,22.47 v1(54.74,22.86)
ARDUINO_IO_8: length 32.3
  TOP w0.127: U25.12 31.55,24.19 31.65,24.28 31.65,25.19 v1(30.95,25.9) ; R78.2 55.02,27.4 54.64,27.4 53.47,26.23 v1(53.47,23.88)
  L4_SIG w0.127: v1(53.47,23.88) 52.62,24.73 42.12,24.73 42,24.84 40.18,24.84 40.14,24.8 36,24.8 35.28,25.51 34.06,25.51 33.83,25.74 33.83,25.91 33.44,26.3 32.93,26.3 32.31,25.68 32.06,25.68 32.03,25.64 31.7,25.64 31.67,25.68 31.16,25.68 v1(30.95,25.9)
ARDUINO_IO_9: length 37.5
  TOP w0.127: U28.12 25.46,24.19 25.55,24.28 25.55,25.5 v1(25.15,25.91) ; v1(53.24,26.77) 53.14,26.87 53.14,28.12 53.53,28.51 54.04,28.51 54.67,29.14 54.67,29.58 55.05,29.97 R72.2
  L4_SIG w0.127: v1(53.24,26.77) 52.45,26.77 52.21,26.53 51.88,26.53 51.86,26.56 51.79,26.62 39.37,26.62 38.61,27.38 35.21,27.38 34.73,27.86 32.67,27.86 32.67,27.86 32.48,27.86 32.48,27.86 32.4,27.86 32.27,27.73 32.27,27.73 31.45,26.91 27.79,26.91 27.47,26.59 25.82,26.59 v1(25.15,25.91)
ARDUINO_IO_10: length 45.1
  TOP w0.127: v1(18.67,33.78) 18.61,33.73 U23.4 ; R68.2 v1(54.74,32)
  L4_SIG w0.127: v1(18.67,33.78) 20.66,33.78 20.99,34.11 22.32,34.11 23.08,33.36 25.36,33.36 25.82,33.82 31.66,33.82 32.52,34.68 38.02,34.68 38.29,34.4 40.71,34.4 41.69,35.38 42.34,35.38 43.23,34.49 46.72,34.49 46.88,34.66 50.43,34.66 51.9,36.13 53.85,36.13 54.48,35.5 54.85,35.5 55.13,35.22 55.13,32.4 v1(54.74,32)
ARDUINO_IO_11: length 41.5
  TOP w0.127: R62.2 v1(54.74,35.05) ; U23.7 18.31,31.78 18.39,31.85 v1(18.41,31.85)
  L4_SIG w0.127: v1(18.41,31.85) 19,32.44 20.81,32.44 21.6,31.66 26.65,31.66 26.89,31.42 27.21,31.42 28.93,33.13 30.11,33.13 30.73,32.51 39.45,32.51 40.53,33.59 42.43,33.59 42.84,34 46.92,34 47.09,34.18 50.58,34.18 51.12,33.64 52.08,33.64 53.07,34.63 54.32,34.63 v1(54.74,35.05)
ARDUINO_IO_12: length 39.5
  TOP w0.127: v1(54.29,33.53) 54.29,35.18 53.98,35.5 53.66,35.5 R58.2 ; v1(21.59,31.18) 21.64,31.13 U23.9
  L4_SIG w0.127: v1(54.29,33.53) 52.29,33.53 52.18,33.41 50.98,33.41 50.46,33.94 48.48,33.94 47.88,33.34 45.91,33.34 45.77,33.2 40.56,33.2 39.65,32.28 30.64,32.28 30.02,32.91 29.02,32.91 27.31,31.19 26.71,31.19 26.49,31.41 21.82,31.41 v1(21.59,31.18)
ARDUINO_IO_13: length 37.4
  TOP w0.127: v1(52.2,35.74) 52.2,36.16 52.55,36.51 53.85,36.51 54.29,36.95 54.29,38.48 54.93,39.12 R51.2 ; U23.12 24.16,33.08 24.29,32.95 v1(24.29,32.83)
  L4_SIG w0.127: v1(52.2,35.74) 52.2,35.13 51.5,34.43 46.98,34.43 46.81,34.26 42.06,34.26 41.87,34.46 41.08,34.46 40.79,34.16 40.39,34.16 39.24,33.02 31.05,33.02 30.48,33.59 25.97,33.59 25.21,32.83 v1(24.29,32.83)
ARDUINO_RTS: length 94.9
  TOP w0.127: R26.2 v1(58.99,52.07) ; U25.5 31.55,27.61 v1(31.24,27.3) ; v1(21.46,45.97) 21.46,46.3 21.73,46.57 U20.14
  L3_SIG w0.127: v1(58.99,52.07) 59.9,51.16 59.9,43.86 59.78,43.74 59.78,42.75 60.16,42.37 60.16,40.68 59.74,40.26 59.74,37.01 60.03,36.72 60.03,33.19 60.01,33.17 60.01,30.98 60.03,30.96 60.03,29.93 59.59,29.48 59.59,28.53 59.99,28.12 v1(59.99,27.56) ; v1(20.62,28.97) 20.62,30.88 20.07,31.43 20.07,34.17 20.48,34.58 20.48,35.11 20.71,35.34 20.71,38.28 20.51,38.48 20.51,42.91 20.79,43.19 20.79,45.3 v1(21.46,45.97)
  L4_SIG w0.127: v1(20.62,28.97) 21.19,28.4 22.31,28.4 24.44,26.28 24.93,26.28 25.47,26.82 27.25,26.82 27.67,27.24 27.67,27.34 28.03,27.7 30.85,27.7 v1(31.24,27.3) 32.03,28.09 32.38,28.09 34.82,28.09 35.31,27.61 38.86,27.61 38.99,27.48 50.29,27.48 50.44,27.33 53.24,27.33 53.9,26.67 53.9,26.32 54.57,25.64 54.9,25.64 55.13,25.87 55.13,27.09 54.76,27.46 54.66,27.46 54.34,27.78 54.34,28.1 54.57,28.33 56.38,28.33 56.59,28.12 59.44,28.12 v1(59.99,27.56)
ARDUINO_VIN: length 1.4
  TOP w0.381: FB13.1 TP1.1
ATP_BLE_INT: length 6.1
  TOP w0.127: U30.32 20.08,12.02 19.69,11.62 17.17,11.62 17.04,11.75 16.83,11.75 16.19,12.38 R263.2
BEST_OF_SUPPLY: length 22.5
  L4_SIG w0.635: v1(13.35,58.08) 9.54,58.08 6.6,61.02 6.6,66.67 9.14,69.22 10.48,69.22 10.92,69.66 J5.2
  BOTTOM w0.254: R143.1 13.1,58.34 v1(13.35,58.08) R15.1
BLE_ATP_INT: length 7.2
  TOP w0.127: U30.31 20.11,12.72 19.94,12.89 19.43,12.89 18.41,11.87 17.27,11.87 16.26,12.89 16.26,13.21 R195.2
BLE_MUX_SEL: length 8.4
  TOP w0.127: v1(32.93,33.53) U38.6 32.51,32.89 32.07,33.34 29.15,33.34 28.7,32.89 U33.6
  BOTTOM w0.127: R282.2 R283.1 R214.2 32.99,33.59 v1(32.93,33.53)
BLE_SWDCLK: length 15.5
  TOP w0.127: v1(26.32,30.53) 26.32,30.53 26.45,30.66 26.45,31.4 26.25,31.59 U33.3 ; J10.4 16.57,29.08 16.92,29.43 18.88,29.43 R269.1 v1(19.24,30.73)
  L4_SIG w0.127: v1(26.32,30.53) 26.32,30.54 25.58,30.54 25.43,30.39 24.47,30.39 23.6,29.52 22.75,29.52 21.94,30.33 20.84,30.33 20.07,31.1 19.6,31.1 v1(19.24,30.73)
BLE_SWDCLK_R: length 24.4
  TOP w0.127: v1(19.75,8.89) 20.08,9.22 U30.36 ; v1(19.62,28.96) 19.94,29.27 19.94,29.59 R269.2
  L3_SIG w0.127: v1(19.62,28.96) 19.88,28.7 19.88,19.3 20.28,18.9 20.28,9.42 v1(19.75,8.89)
  BOTTOM w0.127: R257.1 20.83,8.89 v1(19.75,8.89)
BLE_SWDIO: length 21.5
  TOP w0.127: U38.3 30.11,31.59 v1(29.58,31.06) ; J10.2 15.3,28.64 16.26,29.59 R268.1 16.26,30.42 16.45,30.61 18.22,30.61 v1(18.54,30.92)
  L4_SIG w0.127: v1(29.58,31.06) 29.05,30.53 26.93,30.53 26.28,31.18 24.93,31.18 23.5,29.75 22.85,29.75 22.04,30.56 21.33,30.56 20.86,31.03 20.86,31.75 20.63,31.98 19.6,31.98 v1(18.54,30.92)
BLE_SWDIO_R: length 25
  TOP w0.127: v1(18.61,30.27) 18.32,29.97 R268.2 ; U30.35 19.99,9.92 v1(19.75,10.16)
  L3_SIG w0.127: v1(19.75,10.16) 19.75,11.11 19.32,11.54 19.32,16.63 19.49,16.81 19.49,28.32 18.61,29.2 v1(18.61,30.27)
  BOTTOM w0.127: R253.2 v1(19.75,10.16)
BLE_VIN: length 29.1
  TOP w0.254: U30.3 v1(31.99,9.92)
  TOP w0.381: v1(29.21,21.59) FB14.2 C34.1 29.41,19.23 U30.14
  L3_SIG w0.508: v1(29.21,21.59) 29.21,18.02 30.77,16.46 30.77,16.44 30.87,16.35 30.87,11.04 v1(31.99,9.92)
  L4_SIG w0.381: v1(31.99,9.92) 22.85,9.92 v1(22.73,10.03)
  BOTTOM w0.381: R253.1 22.61,10.16 v1(22.73,10.03) ; C94.1 31.98,9.91 v1(31.99,9.92)
BLE_XIN: length 4.6
  TOP w0.127: C36.1 Y5.2 33.63,15.62 32.51,15.62 31.71,14.82 U30.10
BLE_XOUT: length 5
  TOP w0.127: C41.1 Y5.1 32.61,13.11 32.26,13.46 32.26,13.86 32,14.12 U30.9
CLK_HYB_32M_XTALI: length 5.1
  TOP w0.127: U22.K12 36.42,45.01 R164.2 36.42,47.37 36.27,47.52 36.27,48.66 36.98,49.36 Y2.3
CLK_HYB_32M_XTALO: length 4.6
  TOP w0.127: Y2.1 35.53,48.21 R164.1 35.75,46.88 35.75,44.4 U22.K11
CLK_RTC_32K_XTALI: length 6.4
  TOP w0.127: U22.H2 34.18,36.37 34.18,35.49 34.59,35.08 Y3.2 34.59,31.85 R71.2
CLK_RTC_32K_XTALO: length 6.3
  TOP w0.127: U22.H1 34.58,35.97 36.64,33.91 36.64,33.78 37.08,33.34 Y3.1 37.08,31.83 R71.1
D+PR: length 2.6
  TOP w0.21: L1.4 33.94,64.6 34.03,64.69 34.03,65.73 33.7,66.05 U3.1
D-PR: length 2.6
  TOP w0.21: U3.3 34.7,66.08 34.38,65.76 34.38,64.75 34.49,64.64 L1.1
DM: length 4.7
  TOP w0.21: J1.2 34.53,71.46 34.41,71.34 34.41,69.35 34.7,69.06 34.7,67.78 U3.4
DP: length 4.8
  TOP w0.21: J1.3 33.88,71.45 34.05,71.28 34.05,69.42 33.7,69.07 33.7,67.78 U3.6
EE_CLK: length 12.5
  TOP w0.127: v1(50.57,61.72) 51.22,61.72 U6.4 ; v1(46.61,61.21) 46.1,60.71 46.1,59.69 45.61,59.2 U11.1
  L4_SIG w0.127: v1(46.61,61.21) 47.12,61.72 v1(50.57,61.72)
  BOTTOM w0.127: R271.2 48.01,63.18 49.47,61.72 v1(50.57,61.72)
EE_CS: length 14.1
  TOP w0.127: v1(49.78,63.25) 51.37,63.25 52.26,62.35 U6.5 ; U11.48 48.24,56.92 v1(48.45,56.71)
  L3_SIG w0.127: v1(48.45,56.71) 49.3,57.56 49.3,61.62 50.04,62.36 50.04,62.99 v1(49.78,63.25)
  BOTTOM w0.127: R270.2 48.83,63.69 49.28,63.25 v1(49.78,63.25)
EE_DATA: length 11
  TOP w0.127: U6.3 51.14,64.26 v1(49.78,64.26) ; v1(45.34,59.75) 45.11,59.53 U11.2
  L3_SIG w0.127: v1(45.34,59.75) 45.34,60.99 48.62,64.26 v1(49.78,64.26)
  BOTTOM w0.127: R140.1 49.97,64.45 v1(49.78,64.26)
EE_DATA_R: length 4.1
  TOP w0.127: U6.1 53.21,63.24 52.99,63.02 v1(52.32,63.02)
  BOTTOM w0.127: v1(52.32,63.02) 51.78,63.56 R139.2 R140.2
F_ACBUS2: length 1.7
  TOP w0.127: U11.12 38.38,58.36 TP4.1
F_ACBUS3: length 3.4
  TOP w0.127: U11.11 40.61,59.23 40.24,59.6 39.13,59.6 38.89,59.35 TP3.1
F_JTAG_3P3_M_RST: length 16.6
  TOP w0.127: v1(40.32,53.42) U11.20 ; U37.1 50.1,49.72 49.78,50.04 R208.2 49.21,50.48 48.96,50.74 v1(48.58,50.74)
  L4_SIG w0.127: v1(48.58,50.74) 48.37,50.74 47.98,51.13 46.84,51.13 46.71,51 43.11,51 42.75,51.37 42.75,51.43 40.76,53.42 v1(40.32,53.42)
  BOTTOM w0.127: R151.1 40.02,53.72 v1(40.32,53.42)
  BOTTOM w0.254: R31.2 48.77,50.93 v1(48.58,50.74)
F_JTAG_3P3_M_RST_INV: length 3.4
  TOP w0.127: U17.6 49.29,48 49.15,48.13 48.39,48.13 48.32,48.2 R184.2 R208.1
F_JTAG_3P3_M_RST_INV_R: length 2
  TOP w0.127: U37.4 50.64,48.64 R184.1
F_JTAG_OE_N: length 21.5
  TOP w0.127: v1(42.35,53.28) 40.72,54.92 U11.17
  L3_SIG w0.127: v1(43.05,48.2) 43.05,49.53 42.35,50.23 v1(42.35,53.28)
  L4_SIG w0.127: v1(43.05,48.2) 43.71,47.54 47.3,47.54 47.4,47.64 50.26,47.64 51.01,46.89 52.5,46.89 v1(52.88,47.27)
  BOTTOM w0.127: v1(52.88,47.27) 53.4,46.75 R160.1
F_JTAG_OE_N_R: length 2.8
  TOP w0.127: U39.1 52.39,45.72 v1(52.64,45.47)
  BOTTOM w0.127: R160.2 v1(52.64,45.47) 52.64,46.1 U39.1
F_JTAG_TCK: length 7.7
  TOP w0.127: U13.6 35.25,56.57 36.14,55.68 36.14,54.44 36.78,53.81 36.78,52.88 37.17,52.49 37.17,51.85 37.61,51.42 U11.24
F_JTAG_TDI: length 7.6
  TOP w0.127: U13.7 35.25,56.97 36.42,55.8 36.42,54.61 37.13,53.9 37.13,52.96 37.45,52.64 37.45,52.13 37.67,51.92 U11.23
F_JTAG_TDO: length 14
  TOP w0.127: U17.8 47.92,47.52 47.18,48.26 47.18,50.23 v1(47.69,50.74) ; U11.22 40.35,52.42 v1(40.39,52.45)
  L4_SIG w0.127: v1(40.39,52.45) 41.02,52.45 42.74,50.74 v1(47.69,50.74)
F_JTAG_TMS: length 7
  TOP w0.127: U13.8 35.21,57.37 36.7,55.88 36.7,54.74 37.44,54 37.44,53.11 37.64,52.92 U11.21
F_JTAG_TRST_N: length 7.6
  TOP w0.127: U13.9 34.13,57.75 34.61,58.23 35.56,58.23 35.94,57.85 35.94,57.02 v1(37.27,55.69) 37.5,55.92 U11.15
  BOTTOM w0.127: R148.1 v1(37.27,55.69)
F_JTAG_XCVR_OE_N: length 53
  TOP w0.127: U39.4 v1(53.69,49.63) ; v1(31.47,55.32) 31.81,55.66 31.81,55.88 32.1,56.17 U13.16 32.81,56.17 U13.1 ; U17.1 49.69,45.63 U17.16 49.69,44.41 v1(49.59,44.32)
  L3_SIG w0.127: v1(53.69,49.63) 54.43,50.37 54.43,52.48 53.66,53.25 v1(53.66,60.07)
  L4_SIG w0.127: v1(31.47,55.32) 31.92,55.77 35.78,55.77 36.58,54.97 36.58,54.83 37.06,54.34 38.66,54.34 39.48,55.17 46.18,55.17 49.62,58.61 50.11,58.61 51.31,59.81 51.31,60.34 51.62,60.64 52.05,60.64 52.62,60.07 v1(53.66,60.07)
  BOTTOM w0.127: v1(49.59,44.32) 50.43,43.48 52.64,43.48 52.87,43.71 52.89,43.71 54.07,44.9 54.07,49.24 v1(53.69,49.63) 53.91,49.85 R154.2
F_PWREN_N: length 45.1
  TOP w0.127: R166.1 51.51,44.37 v1(51.5,44.39) ; v1(58.12,54.61) 58.17,54.56 R168.1 ; U11.41 46.09,53.42 45.72,53.78 44.83,53.78 v1(44.39,53.34)
  L3_SIG w0.127: v1(51.5,44.39) 51.5,45.17 52.19,45.86 52.8,45.86 53.04,45.63 53.04,45.17 52.65,44.79 52.65,44.46 52.88,44.23 53.21,44.23 53.92,44.95 53.92,47.15 54.11,47.34 54.11,48.96 55.11,49.95 55.11,52.23 56.78,53.91 57.42,53.91 v1(58.12,54.61)
  L4_SIG w0.127: v1(58.12,54.61) 58.12,55.08 58.31,55.27 58.31,55.6 58.08,55.83 58.06,55.83 57.47,56.43 57.47,59.05 56.9,59.63 55.44,59.63 54.99,60.07 54.74,60.07 52.96,58.29 52.96,54.8 52.24,54.08 45.31,54.08 44.58,53.34 v1(44.39,53.34)
F_UART_3P3_CTS: length 16.5
  TOP w0.127: v1(54.86,57.66) 55.28,57.24 U9.9 ; U11.37 45.61,51.42 v1(45.4,51.63)
  L4_SIG w0.127: v1(54.86,57.66) 53.87,56.67 53.87,53.52 53.13,52.78 51.21,52.78 50.47,52.04 47.67,52.04 47.25,51.63 v1(45.4,51.63)
F_UART_3P3_RTS: length 15.1
  TOP w0.127: U11.38 48.27,51.92 v1(48.56,51.63) ; v1(56.01,58.67) 56.19,58.49 U9.7
  L4_SIG w0.127: v1(56.01,58.67) 56.01,58.04 55,57.04 54.7,57.04 54.1,56.44 54.1,53.43 52.74,52.07 50.82,52.07 50.38,51.63 v1(48.56,51.63)
F_UART_3P3_RX: length 17.5
  TOP w0.127: U9.8 55.79,58.26 55.37,58.67 v1(54.86,58.67) ; U11.39 v1(45.4,52.42)
  L4_SIG w0.127: v1(54.86,58.67) 53.59,57.4 53.59,53.57 53.04,53.01 47.7,53.01 47.11,52.42 v1(45.4,52.42)
F_UART_3P3_TX: length 19.6
  TOP w0.127: U11.40 45.89,52.92 v1(45.43,53.37) ; v1(56.9,58.67) 56.59,58.37 U9.6
  L4_SIG w0.127: v1(45.43,53.37) 48.14,53.37 48.28,53.24 52.94,53.24 53.34,53.64 53.34,58.1 54.36,59.12 56.45,59.12 v1(56.9,58.67)
F_UART_OE_N_R: length 4.6
  TOP w0.127: U39.2 53.04,45.83 53.51,45.35 53.51,44.24 52.91,43.64 R166.2 52.4,42.68 R155.2
F_UART_XCVR_OE_N_R: length 18.5
  TOP w0.127: U9.1 56.99,55.92 U9.16 56.99,55.08 v1(57.33,54.74) 57.28,54.69 R168.2
  L3_SIG w0.127: v1(53.05,44.63) 53.7,45.28 53.7,47.25 53.89,47.44 53.89,49.05 54.86,50.03 54.86,52.32 57.29,54.74 v1(57.33,54.74)
  BOTTOM w0.127: R285.2 57.34,54.72 v1(57.33,54.74) ; v1(53.05,44.63) 52.36,43.94 51.16,43.94 50.9,44.2 R167.1
FT_D+P: length 3.5
  TOP w0.21: U4.1 47.42,66.06 47.76,65.64 47.76,64.65 R8.1 47.76,64.39 47.76,63.35 L2.4
FT_D-P: length 3.4
  TOP w0.21: L2.1 48.11,63.33 48.11,65.73 48.42,66.04 U4.3
FTD_3P3: length 46.9
  TOP w0.203: v1(34.54,55.24) 33.91,55.24 33.73,55.43 U13.3 ; U9.3 v1(57.91,56.84) ; U37.5 51.37,49.72 51.63,49.47
  TOP w0.254: U11.26 40.61,51.22 v1(40.96,51.56) ; v1(40.7,59.75) 41.11,59.34 U11.10 ; v1(51.94,49.47) 51.63,49.47 ; U11.31 43.11,51.37 v1(43.37,51.63) ; U17.3 50.43,46.55 v1(50.61,46.74) ; U11.14 40.03,56.42 v1(40.32,56.71)
  TOP w0.381: U39.5 52.39,49.02 v1(51.94,49.47) ; v1(50.61,46.74) 51.24,46.1 51.24,45.28 50.8,44.83 50.8,43.12 51.24,42.67 R155.1
  TOP w0.508: FB5.1 v1(30.04,64.58)
  L4_SIG w0.508: v1(30.04,64.58) 30.88,63.74 33.7,63.74 34.09,64.14 v1(41.91,64.14)
  BOTTOM w0.254: v1(47.62,49.34) 48.32,50.04 R31.1
  BOTTOM w0.381: C57.1 57.73,57.02 v1(57.91,56.84) ; v1(34.54,55.24) 33.66,56.13 C66.1 ; C71.1 v1(50.61,46.74) 51.12,46.74 R158.1 ; C58.1 v1(40.32,56.71) ; R141.1 30.29,62.93 30.04,63.18 v1(30.04,64.58) ; R161.1 v1(36.58,57.28) ; R186.1 51.87,49.39 v1(51.94,49.47) 52.62,49.47 C96.1 ; R145.1 v1(56.9,60.32) ; R285.1 v1(55.44,53.85) ; R154.1 v1(53.91,52.26) ; C69.1 v1(43.37,51.63)
FTD_AVCC: length 3.6
  TOP w0.127: U11.46 48.22,55.92 v1(48.45,55.69)
  BOTTOM w0.127: R147.2 C59.1 v1(48.45,55.69)
FTD_DM: length 4.3
  TOP w0.21: U4.4 48.42,69.11 48.12,69.41 48.12,71.32 48.24,71.45 J2.2
FTD_DP: length 4.4
  TOP w0.21: U4.6 47.42,69.11 47.76,69.45 47.76,71.28 47.59,71.45 J2.3
FTD_M_RST: length 43.5
  TOP w0.127: U17.15 49.29,44.65 48.95,44.32 48.14,44.32 v1(48.13,44.32)
  L3_SIG w0.127: v1(48.13,44.32) 48.13,50.93 48.06,51 48.06,55.85 48.46,56.26 48.56,56.26 49.53,57.23 49.53,61.34 50.47,62.28 50.47,66.08 51.7,67.31 v1(52.45,67.31)
  L4_SIG w0.127: v1(52.45,67.31) 53.91,68.77 56.13,68.77 56.82,69.45 59.2,69.45 60.26,68.39 60.26,68.07 60.66,67.68 61.33,67.68 62.36,68.71 v1(63.44,68.71)
  BOTTOM w0.127: v1(63.44,68.71) 63.44,69.08 63.03,69.49 63.03,69.83 63.27,70.07 63.28,70.07 63.56,70.35 R128.2
FTD_M_RST_R: length 2.3
  BOTTOM w0.127: R128.1 63.56,72.39 R122.1 62.77,73.37 Q1.1
FTD_USB_5V: length 82.1
  TOP w0.254: v1(44.39,56.71) 44.61,56.93 U11.3 ; U11.42 48.19,53.92 v1(48.45,53.66)
  TOP w0.381: C13.1 54.04,53.72 v1(52.83,53.72) ; v1(51.88,65.53) 51.69,65.72 C3.1 ; U6.6 v1(53.21,60.7)
  TOP w0.508: v1(49.78,65.21) 50.04,65.47 50.04,65.98 FB4.1 ; v1(31.75,67.12) 31.75,67.12 U5.1 ; v1(20.51,67.37) 20.55,67.42 D6.2
  L3_SIG w0.381: v1(44.39,56.71) 43.43,55.75 v1(43.43,53.97)
  L3_SIG w0.508: v1(49.78,65.21) 47.14,68.04 32.67,68.04 v1(31.75,67.12) 30.85,68.02 21.16,68.02 v1(20.51,67.37) ; v1(52.83,53.72) 52.83,60.32 v1(53.21,60.7) 53.21,63.31 51.88,64.64 v1(51.88,65.53)
  L4_SIG w0.508: v1(49.78,65.21) 50.1,65.53 v1(51.88,65.53) ; v1(52.83,53.72) 52.77,53.66 v1(48.45,53.66)
  BOTTOM w0.381: v1(43.43,53.97) 43.37,54.04 R149.1 ; R138.1 31.88,67.25 v1(31.75,67.12) 31.88,66.99 C50.1 ; C65.1 47.82,53.66 v1(48.45,53.66) ; v1(51.88,65.53) 51.69,65.34 R139.1 ; R147.1 46.55,57.4 46.54,57.4 ; C61.1 v1(44.39,56.71) ; v1(53.21,60.7) 53.17,60.7 52.9,60.98 C54.1 ; v1(49.78,65.21) R270.1 R271.1
  BOTTOM w0.508: v1(48.45,53.66) 49.05,54.25 49.05,56.95 48.6,57.4 45.09,57.4 v1(44.39,56.71)
FTD_USB_ID: length 2.9
  TOP w0.127: U35.1 46.67,69.91 46.67,70.74 46.94,71.01 J2.4
FTD_VBUS: length 13.2
  TOP w0.254: U4.5 v1(47.92,68.83)
  TOP w0.381: D1.1 v1(55.04,75.23)
  BOTTOM w0.381: v1(49.47,69.34) 49.47,69.41 51.44,71.37 51.44,72.94 52.2,73.7 52.2,74.8 52.63,75.23 v1(55.04,75.23)
  BOTTOM w0.508: v1(49.47,69.34) 48.43,69.34 v1(47.92,68.83)
FTDI_RESET_N: length 3.1
  TOP w0.127: U11.4 44.11,57.16 43.66,56.71 v1(43.37,56.71)
  BOTTOM w0.127: R149.2 v1(43.37,56.71)
FTDI_XIN: length 9.9
  TOP w0.127: U11.43 50.49,54.42 52.71,52.2 Y1.1 52.71,50.52 v1(52.35,50.16)
  BOTTOM w0.127: v1(52.35,50.16) 52.71,50.52 C16.1
FTDI_XOUT: length 9.5
  TOP w0.127: U11.44 50.6,54.92 50.8,55.12 50.8,57.51 Y1.3 49.53,58.78 C6.1
GPIO25_LED: length 1.1
  TOP w0.127: D4.1 41.4,72.39
GPIO25_LED_R: length 6.4
  TOP w0.127: v1(42.55,70.93) 42.01,70.39 Q4.3 ; D4.2 42.25,75.16 v1(42.35,75.06)
  BOTTOM w0.127: v1(42.55,70.93) 42.55,71.56 42.35,71.75 v1(42.35,75.06)
GPIO26_LED: length 1.1
  TOP w0.127: D3.1 40.13,72.39
GPIO26_LED_R: length 6.5
  TOP w0.127: Q5.3 39.36,70.53 38.95,70.53 v1(38.54,70.93) ; v1(39.24,75.06) 39.34,75.16 D3.2
  BOTTOM w0.127: v1(38.54,70.93) 38.54,72.58 39.24,73.28 v1(39.24,75.06)
IMU_INT1: length 9.9
  TOP w0.127: v1(24.57,49.78) 24.84,50.05 U14.4
  L4_SIG w0.127: v1(24.57,49.78) 27.4,49.78 27.75,50.14 28.86,50.14 v1(29.53,50.8)
  BOTTOM w0.127: v1(29.53,50.8) 29.53,53.34 29.27,53.59 R156.1
IMU_INT2: length 1.7
  TOP w0.127: U14.9 28.39,50.55 v1(28.64,50.8)
  BOTTOM w0.127: R162.1 28.51,50.93 v1(28.64,50.8)
JTAG_TDI_DIR: length 3.4
  TOP w0.127: U13.4 34.3,56.17 U13.5 35.21,56.17 35.56,55.82 v1(35.56,55.24)
  BOTTOM w0.127: R161.2 35.88,55.56 v1(35.56,55.24)
JTAG_TDO_DIR: length 3.3
  TOP w0.127: v1(51.04,47.51) 51.03,47.52 U17.5
  BOTTOM w0.127: R284.1 51.15,49.18 51.15,47.63 v1(51.04,47.51)
M_RST_DIR: length 3.3
  TOP w0.127: v1(52.22,47.28) 52.05,47.11 50.87,47.11 50.84,47.14 50.25,47.14 50.07,46.95 U17.4
  BOTTOM w0.127: v1(52.22,47.28) 52.1,47.41 52.1,47.68 R186.2
MUX_CTRL_1: length 23.1
  TOP w0.127: U23.1 17.38,35.68 17.47,35.77 v1(17.47,36.27)
  L3_SIG w0.127: SW4.1 17.91,20.07 17.54,20.43 17.54,25.45 16.57,26.42 16.57,30.35 17.02,30.8 17.02,35.81 v1(17.47,36.27)
  BOTTOM w0.127: R232.2 18.03,17.91 SW4.1
MUX_CTRL_2: length 36.3
  TOP w0.127: v1(34.49,27.22) 34.15,27.56 U25.1
  L3_SIG w0.127: v1(36.89,17.34) 36.61,17.62 36.61,24.78 34.49,26.91 v1(34.49,27.22)
  L4_SIG w0.127: 17.91,15.49 18.81,16.4 33.54,16.4 34.23,17.08 34.99,17.08 35.48,16.59 36.15,16.59 v1(36.89,17.34)
  BOTTOM w0.127: 17.91,15.49 18.69,16.28 20.68,16.28 R237.2
